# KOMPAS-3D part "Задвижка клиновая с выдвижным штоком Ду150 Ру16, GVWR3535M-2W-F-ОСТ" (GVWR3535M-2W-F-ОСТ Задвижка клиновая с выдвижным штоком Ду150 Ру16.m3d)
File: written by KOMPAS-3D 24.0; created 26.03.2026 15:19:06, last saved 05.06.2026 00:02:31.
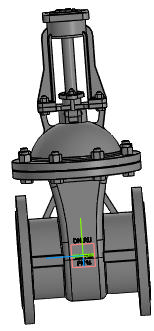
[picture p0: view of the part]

Document properties: Автор: R2D2; Полное имя файла: E:\Работа\Зайцев\GVWR3535M-2W-F-ОСТ Задвижка клиновая 30нж941нж DN.ru Ду50-200 Ру16\исходные данные\DN150\dn150\GVWR3535M-2W-F-ОСТ Задвижка клиновая с выдвижным штоком Ду150 Ру16.m3d

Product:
- Part/product: Задвижка клиновая с выдвижным штоком Ду150 Ру16  | designation GVWR3535M-2W-F-ОСТ
    Масса: 47.5
    Раздел спецификации: Прочие изделия
    Примечание: D040-09829
    additional columns: D040-10013

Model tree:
1. Операция без истории:1

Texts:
  GVWR3535M-2W-F-ОСТ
